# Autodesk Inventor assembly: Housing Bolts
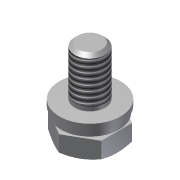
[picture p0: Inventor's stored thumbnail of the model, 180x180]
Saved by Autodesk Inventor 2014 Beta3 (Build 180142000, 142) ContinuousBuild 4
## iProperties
Created: 2011-01
Part Number: Housing Bolts
Document SubType Name: Assembly
Designer: Beta-8540w
ClientObjectVersion: 1
Author: Beta-8540w
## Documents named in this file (4)
- C:\Inventor 2014 Essentials\Assemblies\Chapter 09\Design Accelerators\Bolted Connection c09-02.iam
- C:\Inventor 2014 Essentials\Content Center Files\en-US\ISO 8738\ISO 8738 - 4.ipt
- C:\Inventor 2014 Essentials\Content Center Files\en-US\DIN 128\DIN 128 - A4.ipt
- C:\Inventor 2014 Essentials\Content Center Files\en-US\ISO 4017\ISO 4017 - M4 x 8ISO.ipt
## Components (3 placed, 3 different names)
1. DIN EN 28738 4:1
2. DIN 128 A4:1
3. ISO 4017 M4 x 8:1
